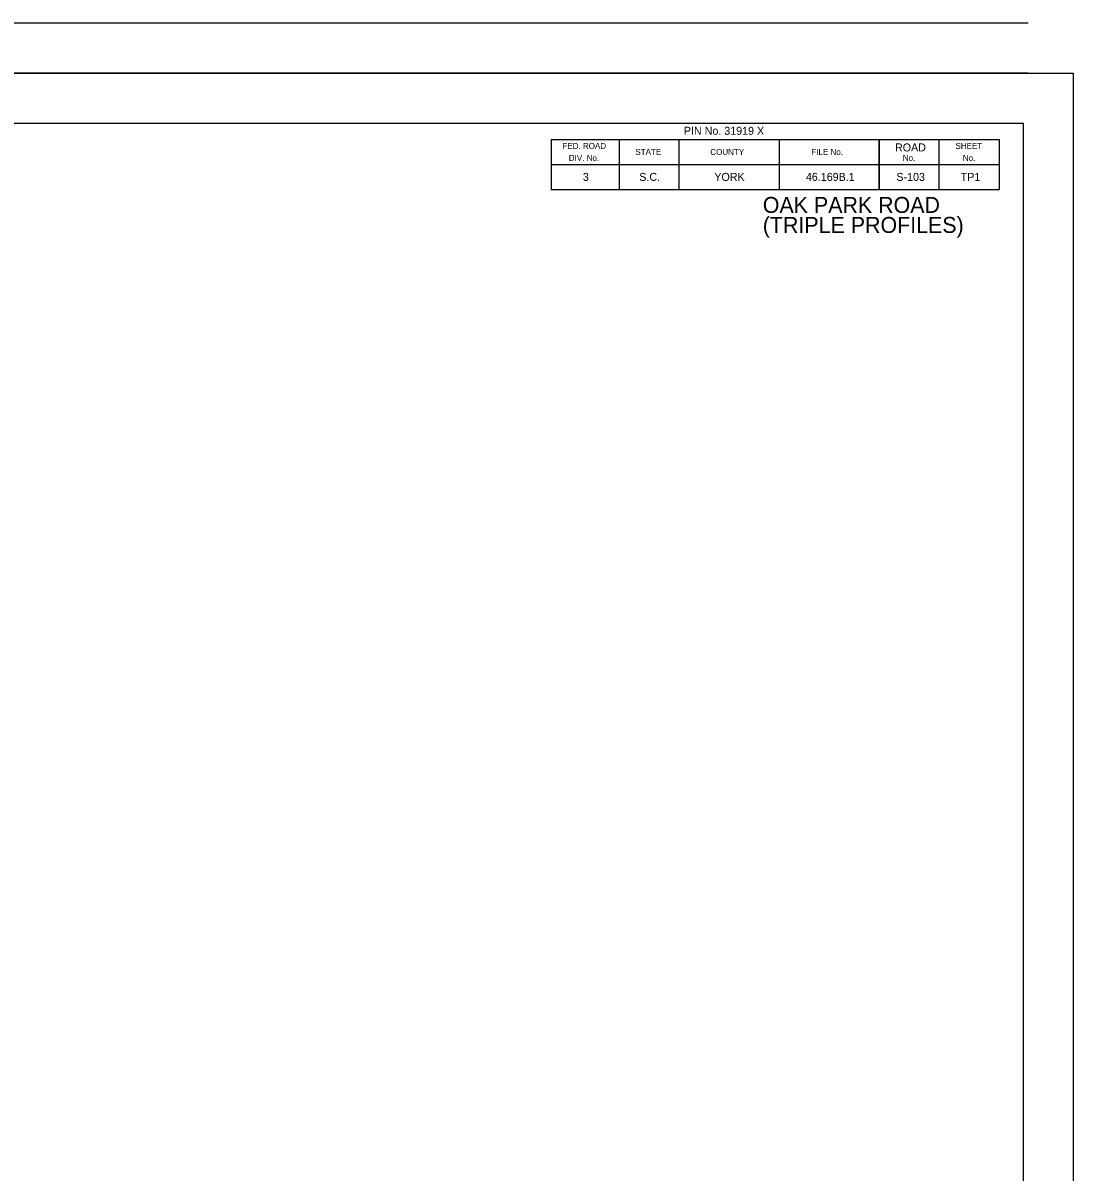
# Model space of a CAD drawing. Extents: x 49817 to 52200, y 49938 to 51088.
# Drawn here: x 51088 to 51613, y 50513 to 51088 of the extents above; entities that cross this region are included whole.
import ezdxf

# ---------------------------------------------------------------- set-up
doc = ezdxf.new("R2010")
doc.units = 0
for name, color, linetype in [('RD_SHT_Bndy', 7, 'Continuous'), ('RD_SHT_Iplotshp', 7, 'Continuous'), ('RD_SHT_TX', 7, 'Continuous')]:
    doc.layers.add(name, color=color, linetype=linetype)

msp = doc.modelspace()

# ---------------------------------------------------------------- linework, layer by layer
at = {"layer": 'RD_SHT_Bndy'}
for p, q in [((51590.65, 51087.5), (49830.65, 51087.5)), ((51590.65, 51062.5), (49830.65, 51062.5)), ((51352.15, 51029.3), (51352.15, 51004.3)), ((51352.15, 51029.3), (51516.15, 51029.3)), ((51386.15, 51029.3), (51386.15, 51004.3)), ((51416.15, 51004.3), (51416.15, 51029.3)), ((51466.15, 51029.3), (51466.15, 51004.3)), ((51516.15, 51004.3), (51516.15, 51029.3)), ((51516.15, 51029.3), (51516.15, 51004.3)), ((51516.15, 51029.3), (51576.15, 51029.3)), ((51546.15, 51004.3), (51546.15, 51029.3)), ((51576.15, 51029.3), (51576.15, 51004.3)), ((51352.15, 51016.8), (51516.15, 51016.8)), ((51516.15, 51016.8), (51576.15, 51016.8)), ((51352.15, 51004.3), (51516.15, 51004.3)), ((51516.15, 51004.3), (51576.15, 51004.3))]:
    msp.add_line(p, q, dxfattribs=at)
msp.add_lwpolyline([(49913.05, 51037.5), (51588, 51037.5), (51588, 49987.5), (49913.05, 49987.5)], close=True, dxfattribs=at)
at = {"layer": 'RD_SHT_Iplotshp'}
msp.add_lwpolyline([(49817.1, 51062.5), (51613, 51062.5), (51613, 49962.5), (49817.1, 49962.5)], close=True, dxfattribs=at)

# ---------------------------------------------------------------- texts
at = {"layer": 'RD_SHT_TX'}
for s, height, p in [('PIN No. 31919 X   ', 4, (51418.42, 51031.6)), ('FED. ROAD', 3, (51357.7, 51024.55)), ('      ROAD      ', 4, (51515.09, 51023.29)), ('SHEET', 3, (51554.23, 51024.55)), ('DIV. No.', 3, (51360.89, 51018.55)), ('STATE', 3, (51394.17, 51021.55)), ('COUNTY', 3, (51431.64, 51021.55)), ('FILE No.', 3, (51482.15, 51021.55)), ('No.', 3, (51527.91, 51018.55)), ('No.', 3, (51557.91, 51018.55)), ('3', 4, (51367.95, 51008.55)), ('S.C.', 4, (51396.13, 51008.55)), ('      YORK     ', 4, (51424.74, 51008.55)), ('   46.169B.1    ', 4, (51474.99, 51008.55)), ('     S-103      ', 4, (51517.27, 51008.55)), ('      TP1       ', 4, (51547.93, 51008.55)), ('OAK PARK ROAD', 8, (51457.89, 50992.53)), ('(TRIPLE PROFILES)', 8, (51457.89, 50982.53))]:
    msp.add_text(s, height=height, dxfattribs=at).set_placement(p)

doc.saveas('drawing.dxf')
